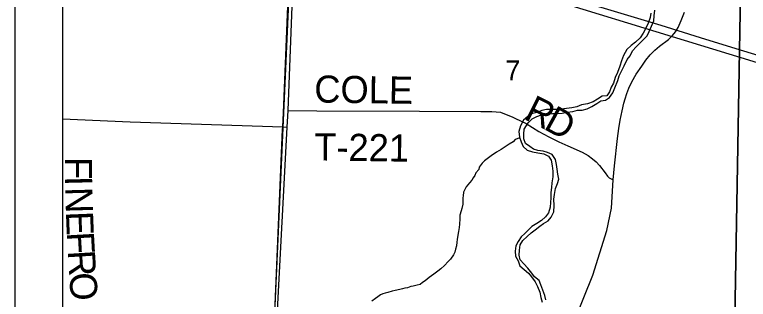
# Model space of a CAD drawing. Extents: x 0 to 34, y 0 to 22.
# Drawn here: x 2 to 3.538, y 18.58 to 19.175 of the extents above; entities that cross this region are included whole.
import ezdxf

# ---------------------------------------------------------------- set-up
doc = ezdxf.new("R2010")
doc.units = 0
for name, color, linetype in [('Default', 7, 'Continuous'), ('GM_X_County_Road', 7, 'Continuous'), ('GM_X_County_Road_Text', 7, 'Continuous'), ('GM_X_Minor_River', 7, 'Continuous'), ('GM_X_Rail_Line', 7, 'Continuous'), ('GM_X_Section', 7, 'Continuous'), ('GM_X_Section_Text', 7, 'Continuous'), ('GM_X_State_Route', 7, 'Continuous'), ('GM_X_Township', 7, 'Continuous'), ('GM_X_Township_Road', 7, 'Continuous'), ('GM_X_Township_Road_Text', 7, 'Continuous'), ('SH_Cut_Line', 7, 'Continuous'), ('SH_Data', 7, 'Continuous')]:
    doc.layers.add(name, color=color, linetype=linetype)

msp = doc.modelspace()

# ---------------------------------------------------------------- linework, layer by layer
at = {"layer": 'Default'}
msp.add_lwpolyline([(2.1, 19.4698), (2.1, 18.4416), (2.54, 18.4332), (2.5413, 18.4578), (2.5849, 19.435)], close=True, dxfattribs=at)
at = {"layer": 'GM_X_County_Road'}
for p, q in [((2.5733, 18.9746), (2.5885, 19.3706)), ((2.5713, 18.9402), (2.5726, 18.9631)), ((2.5726, 18.9631), (2.5733, 18.9746)), ((2.5258, 18.084), (2.5713, 18.9402))]:
    msp.add_line(p, q, dxfattribs=at)
at = {"layer": 'GM_X_Minor_River'}
for points in [[(3.1381, 18.8416), (3.1369, 18.8523), (3.1356, 18.8618), (3.1336, 18.8725), (3.1267, 18.8826), (3.1166, 18.887), (3.1076, 18.8899), (3.0966, 18.8914), (3.0872, 18.8939), (3.0798, 18.8998), (3.0705, 18.9058), (3.0673, 18.9157), (3.0672, 18.9252), (3.0682, 18.9358), (3.0762, 18.9493), (3.0848, 18.9574), (3.0947, 18.9624), (3.1039, 18.966), (3.1138, 18.9676), (3.1271, 18.9684), (3.1378, 18.9684), (3.1476, 18.9693), (3.1583, 18.9713), (3.1701, 18.9729), (3.1793, 18.9753), (3.1892, 18.9758), (3.1998, 18.9781), (3.2098, 18.9836), (3.2202, 18.9897), (3.2284, 18.9952), (3.2386, 18.9964), (3.2467, 19.0019), (3.2538, 19.012), (3.2579, 19.0221), (3.2644, 19.0379), (3.2673, 19.0473), (3.2729, 19.0585), (3.2774, 19.0683), (3.2834, 19.0814), (3.2897, 19.0896), (3.2949, 19.0997), (3.3027, 19.1082), (3.3101, 19.116), (3.3175, 19.1226), (3.3257, 19.1311), (3.3301, 19.1401), (3.3346, 19.1517), (3.3394, 19.1626), (3.3405, 19.1728), (3.3416, 19.185)], [(3.3331, 19.1787), (3.332, 19.1693), (3.3279, 19.158), (3.3227, 19.1475), (3.3171, 19.1366), (3.3108, 19.127), (3.3011, 19.1177), (3.2922, 19.1111), (3.2828, 19.1023), (3.2764, 19.0899), (3.2716, 19.0787), (3.2686, 19.0677), (3.2633, 19.0546), (3.2585, 19.0437), (3.2548, 19.0321), (3.2504, 19.0234), (3.2467, 19.0141)], [(3.2467, 19.0141), (3.2412, 19.0055), (3.2313, 19.0046), (3.2213, 18.9988), (3.2124, 18.993), (3.2009, 18.9887), (3.1883, 18.9864), (3.178, 18.9829), (3.1677, 18.9805), (3.1563, 18.9793), (3.1452, 18.9777), (3.1357, 18.9769), (3.1259, 18.9767), (3.1145, 18.9767), (3.1049, 18.9747), (3.0953, 18.9704), (3.0851, 18.9688), (3.0758, 18.9626), (3.0668, 18.9544), (3.0605, 18.9425), (3.0567, 18.9308), (3.0583, 18.919), (3.0618, 18.909), (3.0657, 18.8998), (3.0743, 18.892), (3.0852, 18.8886), (3.0965, 18.8861), (3.1093, 18.8842), (3.1187, 18.8794), (3.1241, 18.8709), (3.1268, 18.859), (3.1277, 18.8476), (3.1281, 18.8358), (3.1259, 18.8234), (3.1252, 18.8139), (3.1234, 18.8033), (3.1235, 18.7923), (3.1232, 18.7824), (3.1226, 18.7726), (3.1192, 18.7609), (3.1126, 18.752), (3.1044, 18.745), (3.0944, 18.7384), (3.0839, 18.7319), (3.0769, 18.7249), (3.0695, 18.7175), (3.0614, 18.7105), (3.055, 18.7008), (3.0506, 18.6918), (3.0492, 18.6804), (3.05, 18.6702), (3.0551, 18.6602), (3.059, 18.6498), (3.0682, 18.6419), (3.0768, 18.6345), (3.0834, 18.6267), (3.0911, 18.6166), (3.0961, 18.6063), (3.1007, 18.5944), (3.1027, 18.5833), (3.1054, 18.5737)], [(3.0588, 18.9175), (3.0493, 18.9145), (3.0447, 18.9096), (3.0363, 18.9044), (3.0298, 18.8999), (3.0199, 18.8935), (3.0096, 18.8879), (2.9985, 18.8797), (2.9847, 18.8692), (2.9797, 18.8644), (2.9735, 18.8561), (2.9727, 18.8515), (2.9666, 18.8444), (2.9642, 18.8387), (2.9611, 18.8338), (2.9584, 18.8293), (2.9531, 18.8233), (2.9461, 18.815), (2.9407, 18.8037), (2.9399, 18.7965), (2.939, 18.7919), (2.939, 18.7836), (2.9393, 18.779), (2.9369, 18.7699), (2.9361, 18.7646), (2.9333, 18.7555), (2.9329, 18.7479), (2.9324, 18.7373), (2.9315, 18.7297), (2.9299, 18.7218), (2.9291, 18.7142), (2.9271, 18.7051), (2.927, 18.699), (2.9258, 18.6915), (2.9242, 18.6847), (2.9226, 18.6786), (2.9199, 18.6726), (2.9137, 18.6639), (2.9083, 18.659), (2.9006, 18.6504), (2.8933, 18.6432), (2.8868, 18.6384), (2.8784, 18.6324), (2.8685, 18.6253), (2.8601, 18.6185), (2.8551, 18.6148), (2.8501, 18.6107), (2.8436, 18.6092), (2.8349, 18.6074), (2.83, 18.6063), (2.8235, 18.6041), (2.8178, 18.6031), (2.8132, 18.6016), (2.8071, 18.6001), (2.7976, 18.5983), (2.7911, 18.5965), (2.7824, 18.5943), (2.7763, 18.5925), (2.7717, 18.591), (2.7668, 18.5888), (2.7614, 18.5851), (2.7565, 18.5813), (2.7488, 18.5761)], [(3.1135, 18.5784), (3.1111, 18.5876), (3.1069, 18.5987), (3.1026, 18.6099), (3.0991, 18.6191), (3.0894, 18.6266), (3.0836, 18.6343), (3.0755, 18.6448), (3.0674, 18.6541), (3.0597, 18.6627), (3.0577, 18.6722), (3.0584, 18.6828), (3.0598, 18.6934), (3.0653, 18.7028), (3.0739, 18.7113), (3.0825, 18.7186), (3.091, 18.7252), (3.1007, 18.7326), (3.1084, 18.7384), (3.118, 18.7438), (3.1247, 18.7513), (3.1299, 18.7625), (3.1306, 18.7758), (3.1302, 18.7891), (3.1317, 18.7993), (3.1335, 18.8118), (3.1376, 18.8219), (3.1405, 18.8309), (3.1381, 18.8416)]]:
    msp.add_lwpolyline(points, dxfattribs=at)
at = {"layer": 'GM_X_Rail_Line'}
for points in [[(2.1, 19.5368), (2.1257, 19.529), (2.3297, 19.4665), (2.3712, 19.4537), (2.4946, 19.4156), (2.5895, 19.3868), (2.8189, 19.3166), (2.9839, 19.2661), (3.0893, 19.234), (3.17, 19.2094), (3.2494, 19.1851), (3.3541, 19.1532), (3.437, 19.1279), (3.5117, 19.1049), (3.7206, 19.0413), (3.9442, 18.9731), (4.115, 18.921), (4.2732, 18.8725), (4.3809, 18.8396), (4.4591, 18.8158), (4.5185, 18.7976), (5.0181, 18.6458)], [(2.1, 19.5186), (2.8346, 19.2964), (3.6748, 19.0394), (4.5141, 18.7823), (5.7652, 18.3991), (6.2109, 18.2673), (6.7654, 18.1025), (7.4524, 17.8921)]]:
    msp.add_lwpolyline(points, dxfattribs=at)
at = {"layer": 'GM_X_Section'}
for points in [[(3.5253, 19.4614), (3.5082, 18.4594), (2.5413, 18.4578), (2.5849, 19.435), (2.5858, 19.465)], [(4.5252, 19.4639), (4.517, 18.4555), (3.5082, 18.4594), (3.5253, 19.4614)]]:
    msp.add_lwpolyline(points, close=True, dxfattribs=at)
at = {"layer": 'GM_X_State_Route'}
for points in [[(3.2542, 18.8299), (3.257, 18.8589), (3.2635, 18.9163), (3.266, 18.937), (3.269, 18.9549), (3.2732, 18.9743), (3.2769, 18.9902), (3.2793, 18.9991), (3.2829, 19.0108), (3.2869, 19.0214), (3.2933, 19.035), (3.3026, 19.0506), (3.3144, 19.0678), (3.3232, 19.0799), (3.3322, 19.0914), (3.3418, 19.1009), (3.3517, 19.1094), (3.3701, 19.1232), (3.3786, 19.1321), (3.385, 19.1394), (3.3903, 19.1486), (3.397, 19.1634), (3.4039, 19.1808)], [(3.1754, 18.5404), (3.2116, 18.6305), (3.2414, 18.7236), (3.2506, 18.7705), (3.2542, 18.8299)]]:
    msp.add_lwpolyline(points, dxfattribs=at)
at = {"layer": 'GM_X_Township'}
msp.add_lwpolyline([(2.5093, 17.4289), (2.5256, 18.0846), (2.5616, 18.9348), (2.5619, 18.941), (2.5631, 18.9701), (2.6034, 19.9491), (2.6035, 19.9525), (2.6217, 20.3636), (2.6265, 20.3636), (2.7999, 20.363), (2.8069, 20.3629), (2.814, 20.3628), (2.8217, 20.3627), (3.5356, 20.3768), (3.5731, 20.3768), (3.6279, 20.3774), (4.0307, 20.3846), (4.54, 20.3955), (4.5784, 20.3968), (5.284, 20.4086)], dxfattribs=at)
at = {"layer": 'GM_X_Township_Road'}
for p, q in [((2.5713, 18.9402), (2.5726, 18.9631)), ((2.5726, 18.9631), (2.5733, 18.9746))]:
    msp.add_line(p, q, dxfattribs=at)
for points in [[(2.4116, 15.0173), (2.4334, 15.5145), (2.4339, 15.5244), (2.4986, 16.925), (2.5003, 16.9626), (2.5093, 17.4289), (2.5256, 18.0846), (2.5616, 18.9348), (2.5619, 18.941), (2.5631, 18.9701), (2.6034, 19.9491), (2.6035, 19.9525), (2.6217, 20.3636), (2.1208, 20.3735), (2.1108, 20.3737), (2.1, 20.3739), (2.1, 14.5206)], [(2.5733, 18.9746), (2.6335, 18.9742), (2.8485, 18.9732), (2.9771, 18.9727), (3.0001, 18.9729), (3.0182, 18.9715), (3.0443, 18.9608), (3.05, 18.9581)], [(2.1, 18.9571), (2.2423, 18.9515), (2.5621, 18.9405), (2.5713, 18.9402)], [(3.05, 18.9581), (3.0719, 18.9477), (3.0986, 18.9312), (3.1193, 18.9198), (3.1405, 18.909), (3.1593, 18.901), (3.1896, 18.8874), (3.2017, 18.8806), (3.2114, 18.8739), (3.2188, 18.8675), (3.2258, 18.8597), (3.2378, 18.8441), (3.2426, 18.8375), (3.2459, 18.8342), (3.2542, 18.8299)]]:
    msp.add_lwpolyline(points, dxfattribs=at)
at = {"layer": 'SH_Cut_Line'}
msp.add_lwpolyline([(8.9, 20.9), (2.1, 20.9), (2.1, 14.5206)], dxfattribs=at)
at = {"layer": 'SH_Data'}
for p, q in [((2, 21), (2, 14)), ((2.1, 20.9), (2.1, 14.1))]:
    msp.add_line(p, q, dxfattribs=at)

# ---------------------------------------------------------------- texts
at = {"layer": 'GM_X_County_Road_Text'}
for s, rotation, p in [('F', 269.7814, (2.1055, 18.8775)), ('I', 271.4097, (2.1054, 18.8374)), ('N', 271.524, (2.106, 18.814)), ('E', 272.3129, (2.1073, 18.7631)), ('F', 273.2027, (2.1091, 18.7197)), ('R', 273.4766, (2.1113, 18.6811)), ('O', 273.9435, (2.1141, 18.634))]:
    msp.add_text(s, height=0.0568, rotation=rotation, dxfattribs=at).set_placement(p)
at = {"layer": 'GM_X_Section_Text'}
msp.add_text('7', height=0.0419, rotation=0, dxfattribs=at).set_placement((3.0286, 19.0377))
at = {"layer": 'GM_X_Township_Road_Text'}
for s, height, rotation, p in [('COLE', 0.05682, 359.2115, (2.6277, 18.9916)), ('R', 0.0568, 333.6793, (3.0652, 18.9578)), ('D', 0.0568, 331.1796, (3.1065, 18.9374)), ('T-221', 0.05682, 359.1574, (2.6276, 18.8706))]:
    msp.add_text(s, height=height, rotation=rotation, dxfattribs=at).set_placement(p)

doc.saveas('drawing.dxf')
